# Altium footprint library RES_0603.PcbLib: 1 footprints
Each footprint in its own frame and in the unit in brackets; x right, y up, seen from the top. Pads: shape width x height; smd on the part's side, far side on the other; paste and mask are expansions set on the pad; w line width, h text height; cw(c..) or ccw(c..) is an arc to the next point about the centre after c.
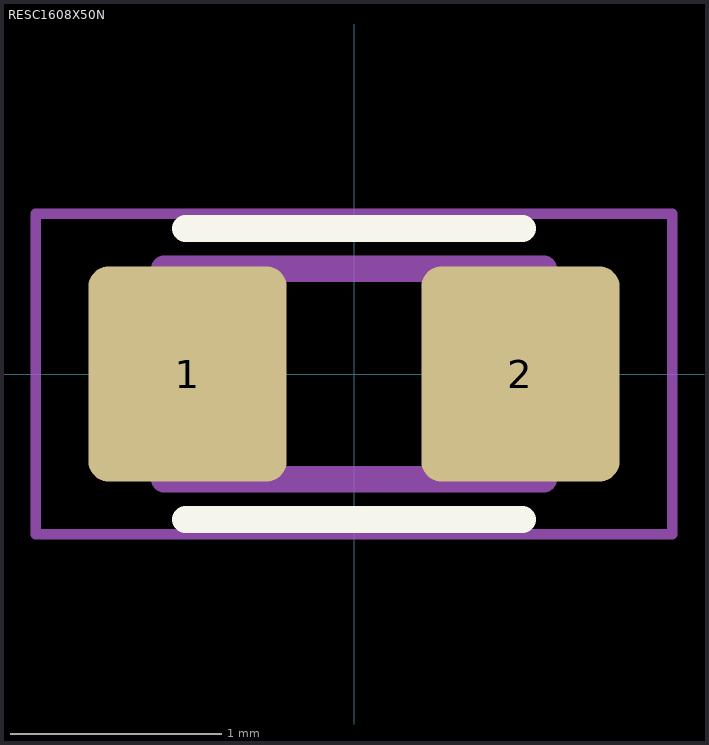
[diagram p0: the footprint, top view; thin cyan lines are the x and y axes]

## RESC1608X50N [mm]
pads (2):
  rrect20% 0.94x1.02 smd: 1(-0.79,0) 2(0.79,0)
Top Overlay:
  lines w0.127: -0.8,-0.69 0.8,-0.69 ; -0.8,0.69 0.8,0.69
Mechanical 13:
  lines w0.127: -0.9,-0.5 -0.9,0.5 0.9,0.5 0.9,-0.5 -0.9,-0.5
Mechanical 15:
  lines w0.05: -1.51,-0.76 -1.51,0.76 1.51,0.76 1.51,-0.76 -1.51,-0.76
3D body "RES_0603.STEP": height 0.78, standoff -0.02, extent -0.792,-0.477 0.808,0.473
